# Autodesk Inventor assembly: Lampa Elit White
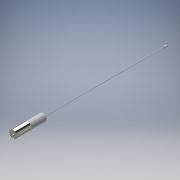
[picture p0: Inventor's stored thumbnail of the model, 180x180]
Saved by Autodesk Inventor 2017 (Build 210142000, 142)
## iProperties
Created: 2020-09
Part Number: Lampa Elit White
Document SubType Name: Assembly
Designer: Admin
Author: Admin
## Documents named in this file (4)
- D:\TK Lighting\Projekty Lamp\Lampa Elit White.iam
- D:\TK Lighting\Logan Black\Klosz srebrny 4367.ipt
- D:\TK Lighting\Logan Black\Klosz.ipt
- D:\TK Lighting\Logan Black\Zawiesie.ipt
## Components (3 placed, 3 different names)
1. Klosz srebrny 4367:1 — Mate:1, Mate:2
2. Klosz:1 — Mate:1, Mate:2, Mate:3, Mate:4
3. Zawiesie:1 — Mate:3, Mate:4
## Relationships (4: Mate 4)
- Mate:1: Klosz srebrny 4367:1 ↔ Klosz:1
- Mate:2: Klosz srebrny 4367:1 ↔ Klosz:1
- Mate:3: Klosz:1 ↔ Zawiesie:1
- Mate:4: Klosz:1 ↔ Zawiesie:1
